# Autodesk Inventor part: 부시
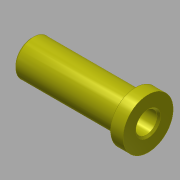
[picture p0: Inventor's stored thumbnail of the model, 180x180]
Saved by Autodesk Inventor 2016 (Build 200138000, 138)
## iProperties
Created: 2016-11
Part Number: 부시
Material: 강철, 연강
Document SubType Name: Modeling
Designer: mduedu
Density: 1 g/cm^3
Appearance: 노란색
Author: mduedu
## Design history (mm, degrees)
sketch "스케치1"
  geometry: L1 (0, 0)-(65, 0); L2 (65, 0)-(65, 14); L3 (65, 14)-(58, 14); L4 (58, 14)-(58, 10); L5 (58, 10)-(0, 10); L6 (0, 10)-(0, 0)
  constraints: 12 end point, 3 parallel, 2 perpendicular, 1 horizontal
  dimensions: "d0" = 65 distance of L1.start L1.end; "d1" = 7 distance of L2.end L3.end; "d2" = 28 diameter of L3 L1; "d3" = 20 diameter of L5 L1
revolve "회전1" sketch "스케치1" stored, may be unused: angle "d4" = 90 deg
hole "구멍1" diameter "d7" = 12; stored, may be unused: countersink angle "d11" = 90 deg, drill point angle "d13" = 118 deg; dims "d5" = 10, "d6" = 10, "d8" = 6, "d9" = 4, "d10" = 2, "d12" = 8
chamfer "모따기1" distance "d14" = 1; stored, may be unused: second distance "d15" = 2, angle "d16" = 45 deg
node "솔리드1"
